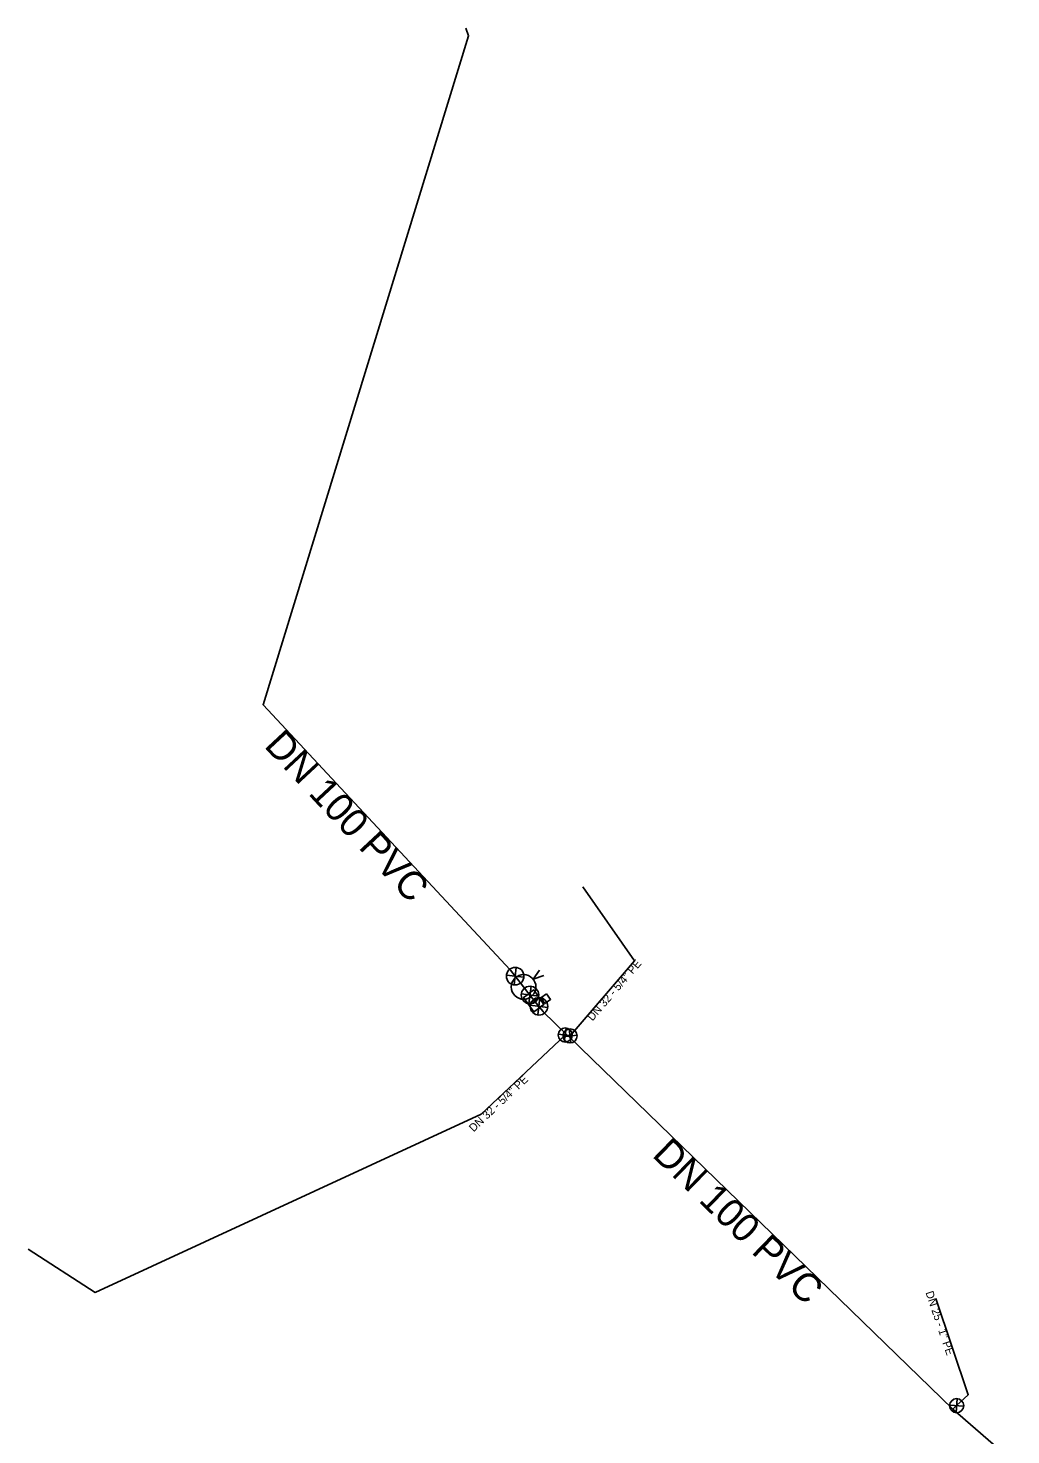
# Model space of a CAD drawing. Extents: x -443519 to -443021, y -1121477 to -1120870.
# Drawn here: x -443516 to -443460.1, y -1120950.3 to -1120870.3 of the extents above; entities that cross this region are included whole.
import ezdxf

# ---------------------------------------------------------------- set-up
doc = ezdxf.new("R2010")
doc.units = 0
for name, color, linetype in [('_pripojka_priblizne_', 7, 'Continuous'), ('_voda_smvak_prevzato_z_dokumentace_', 7, 'Continuous'), ('Default', 7, 'Continuous'), ('MoLevel 27', 7, 'Continuous'), ('MoLevel 30', 7, 'Continuous'), ('MoLevel 32', 7, 'Continuous'), ('MoLevel 42', 7, 'Continuous'), ('MoLevel 43', 7, 'Continuous'), ('MoLevel 46', 7, 'Continuous'), ('MoLevel 53', 7, 'Continuous')]:
    doc.layers.add(name, color=color, linetype=linetype)

# ---------------------------------------------------------------- blocks, each defined once
blk = doc.blocks.new('_uzaver_')
at = {"layer": 'Default'}
for p, q in [((-0.000035, -0.000035), (0.000035, 0.000035)), ((0.000035, -0.000035), (-0.000035, 0.000035))]:
    blk.add_line(p, q, dxfattribs=at)
for radius in [0.00005, 0.0000025]:
    blk.add_circle((0, 0), radius, dxfattribs=at)
blk = doc.blocks.new('_uzaver_pripojka_')
at = {"layer": 'Default'}
for p, q in [((-0.000035, -0.000035), (0.000035, 0.000035)), ((0.000035, -0.000035), (-0.000035, 0.000035))]:
    blk.add_line(p, q, dxfattribs=at)
for radius in [0.00005, 0.0000025]:
    blk.add_circle((0, 0), radius, dxfattribs=at)
blk = doc.blocks.new('_zaslepeni_')
at = {"layer": 'Default'}
blk.add_lwpolyline([(-0.00004, -0.00005), (0, -0.00005), (0, 0.00005), (-0.00004, 0.00005), (-0.00004, 0.00005)], dxfattribs=at)
blk = doc.blocks.new('_sachta_voda_')
at = {"layer": 'Default'}
blk.add_lwpolyline([(-0.00001, 0.000065), (0, 0.000035), (0.00001, 0.000065)], dxfattribs=at)
blk.add_circle((0, 0), 0.000035, dxfattribs=at)
blk = doc.blocks.new('_poklop_voda_')
at = {"layer": 'Default'}
blk.add_lwpolyline([(-0.00002, 0.00002), (0.00002, 0.00002), (0.00002, -0.00002), (-0.00002, -0.00002), (-0.00002, 0.00002)], dxfattribs=at)

msp = doc.modelspace()

# ---------------------------------------------------------------- linework, layer by layer
at = {"layer": '_pripojka_priblizne_'}
for points in [[(-443485.211, -1120927.627), (-443485.15, -1120927.57), (-443481.486, -1120923.299), (-443484.435, -1120919.089)], [(-443485.373, -1120927.471), (-443485.43, -1120927.52), (-443490.213, -1120932.029), (-443512.169, -1120942.161), (-443515.983, -1120939.708)], [(-443463.376, -1120948.808), (-443463.16, -1120948.6), (-443462.497, -1120947.98), (-443464.342, -1120942.508)]]:
    msp.add_lwpolyline(points, dxfattribs=at)
at = {"layer": '_voda_smvak_prevzato_z_dokumentace_'}
for p, q in [((-443487.795, -1120924.787), (-443488.278, -1120924.175)), ((-443487.434, -1120925.244), (-443487.795, -1120924.787)), ((-443487.509, -1120925.789), (-443487.188, -1120925.555)), ((-443487.188, -1120925.555), (-443487.434, -1120925.244)), ((-443487.188, -1120925.555), (-443486.926, -1120925.365)), ((-443486.923, -1120925.89), (-443487.188, -1120925.555))]:
    msp.add_line(p, q, dxfattribs=at)
for points in [[(-443488.561, -1120923.815), (-443502.618, -1120908.739), (-443490.922, -1120870.697), (-443491.082, -1120870.254)], [(-443488.278, -1120924.175), (-443488.548, -1120923.833), (-443488.561, -1120923.815)], [(-443486.681, -1120926.194), (-443486.689, -1120926.187), (-443486.923, -1120925.89)], [(-443460.076, -1120951.668), (-443463.376, -1120948.808), (-443485.211, -1120927.627), (-443485.373, -1120927.471), (-443486.681, -1120926.194)]]:
    msp.add_lwpolyline(points, dxfattribs=at)

# ---------------------------------------------------------------- block references
at = {"layer": 'MoLevel 27', "xscale": 10000, "yscale": 10000, "rotation": -51.893122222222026}
for p in [(-443488.278, -1120924.174), (-443487.432, -1120925.242), (-443486.923, -1120925.89)]:
    msp.add_blockref('_uzaver_', p, dxfattribs=at)
at = {"layer": 'MoLevel 30', "xscale": 19999.999999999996, "yscale": 20000.000000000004, "rotation": -51.69968055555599}
msp.add_blockref('_sachta_voda_', (-443487.795, -1120924.786), dxfattribs=at)
at = {"layer": 'MoLevel 42', "xscale": 10000, "yscale": 10000, "rotation": -53.387032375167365}
msp.add_blockref('_poklop_voda_', (-443486.54, -1120925.45), dxfattribs=at)
at = {"layer": 'MoLevel 43', "xscale": 10000}
for p, yscale, rotation in [((-443487.509, -1120925.789), 10000, -144.88140612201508), ((-443486.926, -1120925.365), 9999.999999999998, 34.9393102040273)]:
    msp.add_blockref('_zaslepeni_', p, dxfattribs=dict(at, yscale=yscale, rotation=rotation))
at = {"layer": 'MoLevel 53', "xscale": 7999.999999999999}
for p, yscale, rotation in [((-443485.43, -1120927.52), 8000, -142.62439114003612), ((-443485.15, -1120927.57), 7999.999999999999, 51.5727436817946), ((-443463.16, -1120948.6), 8000, 40.492604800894)]:
    msp.add_blockref('_uzaver_pripojka_', p, dxfattribs=dict(at, yscale=yscale, rotation=rotation))

# ---------------------------------------------------------------- texts
at = {"layer": 'MoLevel 32'}
for s, rotation, p in [("DN 32 - 5/4'' PE", 49.37542, (-443483.876, -1120926.756)), ("DN 32 - 5/4'' PE", 43.30873, (-443490.644, -1120933.061)), ("DN 25 - 1'' PE", 288.63722, (-443464.937, -1120942.167))]:
    msp.add_text(s, height=0.455, rotation=rotation, dxfattribs=at).set_placement(p)
at = {"layer": 'MoLevel 46'}
for rotation, p in [(312.99636, (-443502.607, -1120911.104)), (315.87149, (-443480.541, -1120934.394))]:
    msp.add_text('DN 100 PVC', height=1.6049, rotation=rotation, dxfattribs=at).set_placement(p)

doc.saveas('drawing.dxf')
